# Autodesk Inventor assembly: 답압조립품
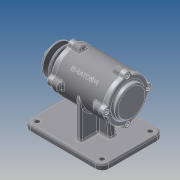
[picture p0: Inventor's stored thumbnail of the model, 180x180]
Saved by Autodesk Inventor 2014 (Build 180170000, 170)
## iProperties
Created: 2015-12
Part Number: 답압조립품
Document SubType Name: Assembly
Designer: user
Author: user
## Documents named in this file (11)
- C:\Users\user\Desktop\공택수\답압조립품.iam
- C:\Users\user\Desktop\공택수\본체.ipt
- C:\Users\user\Desktop\공택수\V-벨트풀리.ipt
- C:\Users\user\Desktop\공택수\너트 M12x1.25.ipt
- C:\Users\user\Desktop\공택수\베어링 6204.ipt
- C:\Users\user\Desktop\공택수\볼트 M4 x 12.ipt
- C:\Users\user\Desktop\공택수\오일실.ipt
- C:\Users\user\Desktop\공택수\축.ipt
- C:\Users\user\Desktop\공택수\커버.ipt
- C:\Users\user\Desktop\공택수\커버2.ipt
- C:\Users\user\Desktop\공택수\키(4 x 4 x 12).ipt
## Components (6 placed, 5 different names)
1. V-벨트풀리:1 — Mate:12, Mate:13, Mate:14, Mate:16
2. KS B 1012 클래스 1 일반 - 미터 M12x1.25:1 — Mate:15, Mate:16
3. KS B 2023 6204 - 20 x 47 x 14:1 — Mate:6, Mate:7, Mate:17
4. KS B 2804 D D - 20 32 8:1 — Mate:2, Mate:3
5. KS B 1311 (I) 4 x 4 x 12:1 — Mate:9, Mate:10, Mate:11, Mate:13
6. KS B 2023 6204 - 20 x 47 x 14:2 — Mate:4, Mate:5, Mate:18
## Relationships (16: Mate 16)
- Mate:2: KS B 2804 D D - 20 32 8:1
- Mate:3: KS B 2804 D D - 20 32 8:1
- Mate:4: KS B 2023 6204 - 20 x 47 x 14:2
- Mate:5: KS B 2023 6204 - 20 x 47 x 14:2
- Mate:6: KS B 2023 6204 - 20 x 47 x 14:1
- Mate:7: KS B 2023 6204 - 20 x 47 x 14:1
- Mate:9: KS B 1311 (I) 4 x 4 x 12:1
- Mate:10: KS B 1311 (I) 4 x 4 x 12:1
- Mate:11: KS B 1311 (I) 4 x 4 x 12:1
- Mate:12: V-벨트풀리:1
- Mate:13: V-벨트풀리:1 ↔ KS B 1311 (I) 4 x 4 x 12:1
- Mate:14: V-벨트풀리:1
- Mate:15: KS B 1012 클래스 1 일반 - 미터 M12x1.25:1
- Mate:16: V-벨트풀리:1 ↔ KS B 1012 클래스 1 일반 - 미터 M12x1.25:1
- Mate:17: KS B 2023 6204 - 20 x 47 x 14:1
- Mate:18: KS B 2023 6204 - 20 x 47 x 14:2
